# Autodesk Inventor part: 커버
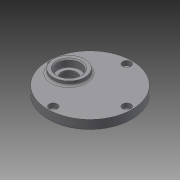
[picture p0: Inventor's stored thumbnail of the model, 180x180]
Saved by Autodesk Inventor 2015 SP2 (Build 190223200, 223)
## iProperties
Created: 2015-06
Part Number: 커버
Material: 일반
Document SubType Name: Modeling
Designer: AMC
Density: 1 g/cm^3
Appearance: 기본값
Author: AMC
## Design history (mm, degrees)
sketch "스케치1"
  geometry: C1 r 40 at (0, 0); 1 further point
  constraints: 1 centre point, 1 coincident
  dimensions: "d0" = 80 diameter of C1
extrude "돌출1" new body sketch "스케치1" distance "d1" = 9; taper "d2" = 0 deg
sketch "스케치5"
  geometry: C1 r 14 at (-11, 0); C2 r 14 at (20, 0); 1 further point
  constraints: 2 centre point, 2 horizontal alignment
  dimensions: "d23" = 28 diameter of C1; "d24" = 28 diameter of C2; "d25" = 11 distance of point (0, 0) C1.centre; "d26" = 20 distance of point (0, 0) C2.centre
extrude "돌출3" join sketch "스케치5" distance "d27" = 3; taper "d28" = 0 deg
sketch "스케치6"
  geometry: C1 r 14 at (0, 0) reference; C2 r 14 at (31, 0) reference; 2 further points
  constraints: 1 coincident
hole "구멍3" sketch "스케치6" at (0, 0) diameter "d29" = 18; stored, may be unused: countersink angle "d33" = 90 deg, drill point angle "d35" = 0 deg; dims "d30" = 6, "d31" = 22, "d32" = 7, "d34" = 8
sketch "스케치8"
  geometry: C1 r 15 at (-20, 0); 1 further point
  constraints: 1 centre point, 1 horizontal alignment
  dimensions: "d43" = 30 diameter of C1; "d44" = 20 distance of point (0, 0) C1.centre
extrude "돌출4" join sketch "스케치8" distance "d45" = 4; taper "d46" = 0 deg
sketch "스케치9"
  geometry: C1 r 15 at (0, 0) reference; 2 further points
  constraints: 1 coincident
hole "구멍5" sketch "스케치9" at (0, 0) diameter "d47" = 15; stored, may be unused: countersink angle "d51" = 90 deg, drill point angle "d53" = 118 deg; dims "d48" = 6, "d49" = 22, "d50" = 7, "d52" = 8
sketch "스케치10"
  geometry: C1 r 14 at (-31, 0) reference; C2 r 14 at (0, 0) reference; 3 further points
  constraints: 1 coincident, 1 horizontal alignment
hole "구멍6" sketch "스케치10" at (0, 0) diameter "d54" = 15; stored, may be unused: countersink angle "d58" = 90 deg, drill point angle "d60" = 118 deg; dims "d55" = 6, "d56" = 22, "d57" = 7, "d59" = 9
fillet "모깎기1" dims "d61" = 2
fillet "모깎기2" dims "d62" = 2
fillet "모깎기3" dims "d63" = 0.3
chamfer "모따기1" distance "d64" = 1; stored, may be unused: second distance "d65" = 2, angle "d66" = 45 deg
sketch "스케치11"
  geometry: C1 r 11 at (-20, 0) reference; C2 r 40 at (0, 0) reference; C3 r 17 at (-20, 0) reference; 2 further points
  constraints: 1 vertical alignment
  dimensions: "d67" = 35 distance of point (0, 0) point (0, 35)
hole "구멍7" sketch "스케치11" at (0, 35) diameter "d68" = 4.5; stored, may be unused: countersink angle "d72" = 90 deg, drill point angle "d74" = 118 deg; dims "d69" = 6, "d70" = 8, "d71" = 4.4, "d73" = 9
node "솔리드1"
pattern_circular "원형 패턴1" dims angle "d76" = 360 deg
node "절단 모서리 투영3"
node "절단 모서리 투영5"
node "절단 모서리 투영6"
node "절단 모서리 투영7"
